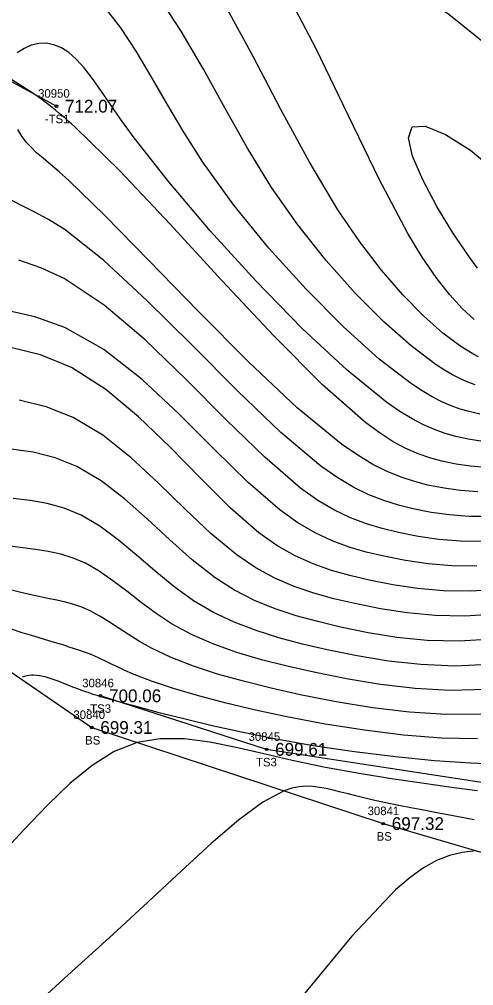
# Model space of a CAD drawing. Extents: x 1376587 to 1378239, y 1000335 to 1003031.
# Drawn here: x 1377322.4 to 1377375.8, y 1001837.8 to 1001951.3 of the extents above; entities that cross this region are included whole.
import ezdxf

# ---------------------------------------------------------------- set-up
doc = ezdxf.new("R2010")
doc.units = 0
for name, color, linetype in [('RD_DTM_BkLn2', 7, 'Continuous'), ('RD_DTM_BkLn_txCode', 7, 'Continuous'), ('RD_DTM_Major1', 7, 'Continuous'), ('RD_DTM_Minor1', 7, 'Continuous'), ('RD_EX_TX_Misc_ELEV', 7, 'Continuous'), ('RD_SMD_Locator', 7, 'Continuous')]:
    doc.layers.add(name, color=color, linetype=linetype)

msp = doc.modelspace()

# ---------------------------------------------------------------- linework, layer by layer
at = {"layer": 'RD_DTM_BkLn2'}
for points in [[(1377217.95, 1001935.1), (1377221.31, 1001940.54), (1377226.58, 1001945.02), (1377238.49, 1001943.91), (1377252.94, 1001946.54), (1377276.28, 1001949.21), (1377302.44, 1001954.41), (1377326.81, 1001941.11)], [(1377299.85, 1001879.9), (1377276.73, 1001887.11), (1377261.32, 1001895.39), (1377258.69, 1001901.66), (1377272.38, 1001899.27), (1377299.03, 1001890.02), (1377330.96, 1001868.15), (1377365.22, 1001856.86), (1377402.11, 1001846.07)], [(1377405.54, 1001849.57), (1377381.1, 1001861.03), (1377351.51, 1001865.58), (1377331.99, 1001871.87)]]:
    msp.add_lwpolyline(points, dxfattribs=at)
at = {"layer": 'RD_DTM_Major1'}
for points in [[(1377376.03, 1001908.38), (1377375.17, 1001908.71), (1377374.28, 1001909.1), (1377373.37, 1001909.56), (1377372.41, 1001910.11), (1377371.42, 1001910.75), (1377368.49, 1001912.95), (1377365.27, 1001915.79), (1377361.91, 1001919.16), (1377358.5, 1001922.99), (1377355.19, 1001927.16), (1377352.08, 1001931.58), (1377349.25, 1001936.17), (1377346.62, 1001940.83), (1377344.08, 1001945.44), (1377341.48, 1001949.91), (1377338.72, 1001954.15), (1377335.66, 1001958.04), (1377332.64, 1001961.12), (1377329.47, 1001963.83), (1377326.29, 1001966.15), (1377323.6, 1001967.83)], [(1377377.67, 1001892.91), (1377375.3, 1001892.93), (1377373.02, 1001893.11), (1377370.84, 1001893.41), (1377368.74, 1001893.83), (1377367.01, 1001894.26), (1377365.28, 1001894.79), (1377363.54, 1001895.48), (1377361.75, 1001896.35), (1377359.88, 1001897.46), (1377357.89, 1001898.85), (1377353.2, 1001902.79), (1377348.08, 1001907.69), (1377342.75, 1001913.03), (1377337.44, 1001918.31), (1377332.39, 1001923), (1377327.82, 1001926.6), (1377325.88, 1001927.81), (1377324.11, 1001928.75), (1377322.55, 1001929.53), (1377321.2, 1001930.25)], [(1377378.09, 1001878.51), (1377374.13, 1001878.27), (1377370.38, 1001878.37), (1377366.82, 1001878.73), (1377363.43, 1001879.28), (1377360.19, 1001879.95), (1377357.54, 1001880.58), (1377354.99, 1001881.28), (1377352.51, 1001882.1), (1377350.1, 1001883.08), (1377347.75, 1001884.28), (1377345.46, 1001885.73), (1377342.77, 1001887.83), (1377340.12, 1001890.19), (1377337.47, 1001892.64), (1377334.8, 1001895), (1377332.05, 1001897.11), (1377329.21, 1001898.8), (1377326.66, 1001899.81), (1377324.07, 1001900.47), (1377321.5, 1001900.85)], [(1377379.3, 1001863.82), (1377375.51, 1001863.95), (1377371.24, 1001864.24), (1377366.64, 1001864.69), (1377361.84, 1001865.29), (1377356.98, 1001866.01), (1377352.2, 1001866.86), (1377348.56, 1001867.59), (1377345.12, 1001868.36), (1377341.92, 1001869.12), (1377339.04, 1001869.85), (1377336.51, 1001870.52), (1377334.42, 1001871.09), (1377333.76, 1001871.27), (1377333.15, 1001871.44), (1377332.59, 1001871.59), (1377332.08, 1001871.74), (1377331.59, 1001871.89), (1377331.12, 1001872.04), (1377330.64, 1001872.2), (1377330.16, 1001872.37), (1377329.68, 1001872.54), (1377329.21, 1001872.72), (1377328.74, 1001872.9), (1377328.26, 1001873.09), (1377327.58, 1001873.36), (1377326.89, 1001873.63), (1377326.19, 1001873.87), (1377325.49, 1001874.08), (1377324.8, 1001874.22), (1377324.13, 1001874.28), (1377323.86, 1001874.28), (1377323.58, 1001874.26), (1377323.32, 1001874.22), (1377323.05, 1001874.15), (1377322.79, 1001874.06)]]:
    msp.add_lwpolyline(points, dxfattribs=at)
at = {"layer": 'RD_DTM_Minor1'}
for points in [[(1377377.21, 1001962.89), (1377369.19, 1001964.7), (1377361.36, 1001966.57), (1377354.64, 1001968.1), (1377349.97, 1001968.88), (1377348.26, 1001968.52), (1377350.56, 1001966.42), (1377356.34, 1001962.73), (1377364.25, 1001957.78), (1377372.91, 1001951.91), (1377380.97, 1001945.44)], [(1377375.91, 1001916.07), (1377374.49, 1001917.37), (1377373, 1001919), (1377371.42, 1001920.99), (1377369.79, 1001923.37), (1377368.09, 1001926.15), (1377364.72, 1001932.56), (1377361.14, 1001939.97), (1377357.34, 1001947.83), (1377353.29, 1001955.56)], [(1377376.56, 1001904.94), (1377375.31, 1001905.24), (1377374.26, 1001905.55), (1377373.2, 1001905.94), (1377372.11, 1001906.41), (1377370.97, 1001906.99), (1377369.78, 1001907.68), (1377368.52, 1001908.51), (1377364.73, 1001911.42), (1377360.53, 1001915.19), (1377356.15, 1001919.61), (1377351.79, 1001924.44), (1377347.67, 1001929.49), (1377344.03, 1001934.53), (1377341.78, 1001938.05), (1377339.79, 1001941.42), (1377337.96, 1001944.61), (1377336.19, 1001947.58), (1377334.38, 1001950.31), (1377332.44, 1001952.76)], [(1377376.43, 1001911.69), (1377375.75, 1001912.04), (1377375.06, 1001912.45), (1377374.33, 1001912.91), (1377372.23, 1001914.47), (1377369.95, 1001916.49), (1377367.53, 1001918.96), (1377365.02, 1001921.86), (1377362.46, 1001925.2), (1377359.9, 1001928.95), (1377356.51, 1001934.63), (1377353.19, 1001940.74), (1377349.92, 1001946.94), (1377346.69, 1001952.91)], [(1377376.7, 1001901.76), (1377375.21, 1001902), (1377373.74, 1001902.33), (1377372.5, 1001902.69), (1377371.25, 1001903.13), (1377369.96, 1001903.7), (1377368.61, 1001904.4), (1377367.18, 1001905.26), (1377365.65, 1001906.31), (1377360.96, 1001910.11), (1377355.7, 1001915.02), (1377350.23, 1001920.62), (1377344.89, 1001926.49), (1377340.01, 1001932.22), (1377335.96, 1001937.39), (1377334.47, 1001939.45), (1377333.18, 1001941.31), (1377332.04, 1001942.96), (1377331.02, 1001944.4), (1377330.06, 1001945.63), (1377329.13, 1001946.65), (1377328.27, 1001947.4), (1377327.39, 1001947.96), (1377326.51, 1001948.33), (1377325.63, 1001948.51), (1377324.74, 1001948.48), (1377323.85, 1001948.26), (1377323.03, 1001947.88), (1377322.19, 1001947.39)], [(1377377.24, 1001898.7), (1377375.48, 1001898.84), (1377373.77, 1001899.09), (1377372.1, 1001899.44), (1377370.71, 1001899.82), (1377369.31, 1001900.3), (1377367.89, 1001900.92), (1377366.4, 1001901.71), (1377364.84, 1001902.7), (1377363.16, 1001903.92), (1377358.09, 1001908.38), (1377352.35, 1001914.15), (1377346.26, 1001920.66), (1377340.13, 1001927.31), (1377334.26, 1001933.51), (1377328.96, 1001938.68), (1377328.57, 1001939.03), (1377328.19, 1001939.37), (1377327.82, 1001939.69), (1377327.44, 1001940.01), (1377327.07, 1001940.33), (1377326.71, 1001940.63), (1377326.3, 1001940.96), (1377325.9, 1001941.28), (1377325.5, 1001941.59), (1377325.09, 1001941.89), (1377324.69, 1001942.19), (1377324.28, 1001942.48), (1377321.02, 1001944.56)], [(1377376.31, 1001922.08), (1377375.35, 1001923.37), (1377373.41, 1001926.22), (1377371.51, 1001929.35), (1377369.86, 1001932.45), (1377368.67, 1001935.24), (1377368.18, 1001937.41), (1377368.6, 1001938.67), (1377370.14, 1001938.78), (1377372.55, 1001937.8), (1377375.46, 1001935.94), (1377378.5, 1001933.44)], [(1377376.32, 1001895.82), (1377374.3, 1001895.97), (1377372.36, 1001896.24), (1377370.46, 1001896.62), (1377368.89, 1001897.03), (1377367.31, 1001897.54), (1377365.69, 1001898.2), (1377364, 1001899.04), (1377362.22, 1001900.11), (1377360.3, 1001901.44), (1377355.12, 1001905.7), (1377349.38, 1001911.09), (1377343.45, 1001917.03), (1377337.7, 1001922.95), (1377332.51, 1001928.26), (1377328.25, 1001932.39), (1377327.12, 1001933.4), (1377326.12, 1001934.25), (1377325.24, 1001934.99), (1377324.48, 1001935.65), (1377323.82, 1001936.28), (1377323.26, 1001936.9), (1377322.73, 1001937.61), (1377322.26, 1001938.36)], [(1377376.94, 1001890), (1377374.28, 1001890.04), (1377371.75, 1001890.24), (1377369.33, 1001890.59), (1377367.01, 1001891.04), (1377365.11, 1001891.5), (1377363.24, 1001892.06), (1377361.38, 1001892.77), (1377359.48, 1001893.67), (1377357.53, 1001894.82), (1377355.49, 1001896.26), (1377351.29, 1001899.88), (1377346.76, 1001904.28), (1377342.04, 1001909.03), (1377337.22, 1001913.67), (1377332.41, 1001917.76), (1377327.73, 1001920.86), (1377324.97, 1001922.12), (1377322.38, 1001923.01)], [(1377376.21, 1001887.09), (1377373.27, 1001887.13), (1377370.48, 1001887.37), (1377367.83, 1001887.76), (1377365.29, 1001888.25), (1377363.22, 1001888.75), (1377361.2, 1001889.34), (1377359.2, 1001890.08), (1377357.2, 1001891.01), (1377355.17, 1001892.19), (1377353.09, 1001893.67), (1377349.33, 1001896.93), (1377345.36, 1001900.83), (1377341.21, 1001904.98), (1377336.88, 1001909.01), (1377332.39, 1001912.52), (1377327.78, 1001915.14), (1377324.26, 1001916.37), (1377320.83, 1001917.14)], [(1377378.91, 1001884.36), (1377375.5, 1001884.16), (1377372.28, 1001884.21), (1377369.23, 1001884.48), (1377366.33, 1001884.92), (1377363.57, 1001885.46), (1377361.31, 1001885.98), (1377359.12, 1001886.6), (1377356.97, 1001887.37), (1377354.85, 1001888.32), (1377352.73, 1001889.53), (1377350.59, 1001891.02), (1377347.23, 1001893.94), (1377343.77, 1001897.38), (1377340.19, 1001901.05), (1377336.47, 1001904.64), (1377332.61, 1001907.86), (1377328.57, 1001910.42), (1377324.94, 1001911.92), (1377321.24, 1001912.82)], [(1377378.49, 1001881.44), (1377374.8, 1001881.21), (1377371.32, 1001881.29), (1377368.02, 1001881.6), (1377364.88, 1001882.09), (1377361.88, 1001882.7), (1377359.43, 1001883.27), (1377357.07, 1001883.93), (1377354.75, 1001884.72), (1377352.49, 1001885.69), (1377350.25, 1001886.9), (1377348.03, 1001888.39), (1377344.99, 1001890.9), (1377341.92, 1001893.8), (1377338.79, 1001896.85), (1377335.58, 1001899.81), (1377332.25, 1001902.46), (1377328.76, 1001904.56), (1377325.62, 1001905.8), (1377322.43, 1001906.57)], [(1377377.66, 1001875.55), (1377373.59, 1001875.37), (1377369.65, 1001875.53), (1377365.84, 1001875.95), (1377362.16, 1001876.56), (1377358.62, 1001877.28), (1377355.73, 1001877.95), (1377352.95, 1001878.68), (1377350.28, 1001879.52), (1377347.71, 1001880.5), (1377345.26, 1001881.66), (1377342.92, 1001883.04), (1377340.61, 1001884.71), (1377338.39, 1001886.53), (1377336.22, 1001888.4), (1377334.07, 1001890.19), (1377331.91, 1001891.79), (1377329.7, 1001893.09), (1377327.73, 1001893.89), (1377325.72, 1001894.45), (1377323.71, 1001894.81), (1377321.72, 1001895.03)], [(1377377.24, 1001872.61), (1377373.1, 1001872.5), (1377368.97, 1001872.72), (1377364.9, 1001873.19), (1377360.91, 1001873.85), (1377357.05, 1001874.63), (1377353.91, 1001875.34), (1377350.9, 1001876.11), (1377348.02, 1001876.97), (1377345.31, 1001877.93), (1377342.77, 1001879.03), (1377340.41, 1001880.3), (1377338.53, 1001881.53), (1377336.76, 1001882.83), (1377335.07, 1001884.14), (1377333.44, 1001885.39), (1377331.83, 1001886.51), (1377330.21, 1001887.44), (1377328.78, 1001888.04), (1377327.32, 1001888.49), (1377325.84, 1001888.82), (1377324.36, 1001889.06), (1377322.87, 1001889.25), (1377321.39, 1001889.44)], [(1377376.81, 1001869.7), (1377372.61, 1001869.67), (1377368.31, 1001869.95), (1377363.97, 1001870.47), (1377359.67, 1001871.18), (1377355.47, 1001872), (1377352.06, 1001872.76), (1377348.81, 1001873.57), (1377345.75, 1001874.43), (1377342.9, 1001875.37), (1377340.31, 1001876.37), (1377337.99, 1001877.46), (1377336.58, 1001878.25), (1377335.28, 1001879.06), (1377334.08, 1001879.85), (1377332.94, 1001880.6), (1377331.84, 1001881.28), (1377330.76, 1001881.85), (1377329.81, 1001882.26), (1377328.85, 1001882.59), (1377327.86, 1001882.86), (1377326.85, 1001883.09), (1377325.81, 1001883.31), (1377324.74, 1001883.53), (1377323.63, 1001883.77), (1377322.47, 1001884.03), (1377321.25, 1001884.34)], [(1377376.28, 1001866.81), (1377372.06, 1001866.9), (1377367.6, 1001867.25), (1377363.01, 1001867.82), (1377358.4, 1001868.55), (1377353.89, 1001869.4), (1377350.22, 1001870.19), (1377346.75, 1001871.01), (1377343.52, 1001871.86), (1377340.58, 1001872.73), (1377337.98, 1001873.6), (1377335.75, 1001874.45), (1377334.86, 1001874.84), (1377334.05, 1001875.22), (1377333.29, 1001875.58), (1377332.59, 1001875.93), (1377331.92, 1001876.25), (1377331.26, 1001876.55), (1377330.69, 1001876.78), (1377330.12, 1001877), (1377329.54, 1001877.2), (1377328.94, 1001877.4), (1377328.32, 1001877.6), (1377327.66, 1001877.8), (1377326.57, 1001878.13), (1377325.39, 1001878.48), (1377324.14, 1001878.86), (1377322.8, 1001879.27), (1377321.4, 1001879.72)], [(1377376.28, 1001860.71), (1377375.68, 1001860.79), (1377372.97, 1001861.16), (1377369.77, 1001861.6), (1377366.2, 1001862.12), (1377362.38, 1001862.74), (1377358.45, 1001863.45), (1377354.52, 1001864.27), (1377351.18, 1001865.05), (1377347.95, 1001865.81), (1377344.84, 1001866.43), (1377341.86, 1001866.81), (1377339.01, 1001866.83), (1377336.31, 1001866.39), (1377333.6, 1001865.33), (1377330.99, 1001863.7), (1377328.4, 1001861.57), (1377325.75, 1001859.03), (1377322.98, 1001856.13), (1377320.01, 1001852.96), (1377315.9, 1001848.66), (1377311.67, 1001844.23), (1377307.64, 1001839.87), (1377304.12, 1001835.76)], [(1377375.91, 1001857.29), (1377373.44, 1001857.78), (1377371.13, 1001858.21), (1377369.76, 1001858.46), (1377368.46, 1001858.7), (1377367.24, 1001858.94), (1377366.07, 1001859.17), (1377364.96, 1001859.4), (1377363.89, 1001859.64), (1377362.94, 1001859.87), (1377362.01, 1001860.11), (1377361.11, 1001860.35), (1377360.22, 1001860.57), (1377359.35, 1001860.78), (1377358.49, 1001860.97), (1377357.73, 1001861.11), (1377356.96, 1001861.21), (1377356.18, 1001861.24), (1377355.35, 1001861.18), (1377354.48, 1001861.01), (1377353.56, 1001860.7), (1377351.07, 1001859.36), (1377348.21, 1001857.26), (1377344.99, 1001854.53), (1377341.45, 1001851.29), (1377337.59, 1001847.69), (1377333.45, 1001843.85), (1377328.16, 1001839.06), (1377322.86, 1001834.2)], [(1377376.1, 1001853.67), (1377374.51, 1001853.48), (1377372.99, 1001853.11), (1377371.48, 1001852.52), (1377369.96, 1001851.68), (1377368.37, 1001850.54), (1377366.67, 1001849.09), (1377361.51, 1001843.66), (1377355.62, 1001836.48)]]:
    msp.add_lwpolyline(points, dxfattribs=at)
at = {"layer": 'RD_SMD_Locator'}
for centre in [(1377326.81, 1001941.11), (1377331.99, 1001871.87), (1377330.96, 1001868.15), (1377351.51, 1001865.58), (1377365.22, 1001856.86)]:
    msp.add_circle(centre, 0.15, dxfattribs=at)

# ---------------------------------------------------------------- texts
at = {"layer": 'RD_DTM_BkLn_txCode'}
for s, p in [('30950', (1377324.65, 1001942.11)), ('-TS1', (1377325.44, 1001939.11)), ('30846', (1377329.84, 1001872.87)), ('-TS3', (1377330.33, 1001869.87)), ('30840', (1377328.8, 1001869.15)), ('BS', (1377330.18, 1001866.15)), ('30845', (1377349.39, 1001866.58)), ('TS3', (1377350.26, 1001863.58)), ('30841', (1377363.38, 1001857.86)), ('BS', (1377364.44, 1001854.86))]:
    msp.add_text(s, height=1, dxfattribs=at).set_placement(p)
at = {"layer": 'RD_EX_TX_Misc_ELEV'}
for s, p in [('712.07', (1377327.81, 1001940.36)), ('700.06', (1377332.99, 1001871.12)), ('699.31', (1377331.96, 1001867.4)), ('699.61', (1377352.51, 1001864.83)), ('697.32', (1377366.22, 1001856.11))]:
    msp.add_text(s, height=1.5, dxfattribs=at).set_placement(p)

doc.saveas('drawing.dxf')
